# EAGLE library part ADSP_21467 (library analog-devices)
SHARC Processor Auto generated by make-symbol-device-package-bsdl.ulp Rev. 33 Source: ADSP_21467_324_CSPBGA_bsdl.txt http://www.analog.com/static/imported-files/data_sheets/ADSP_21462W_21465W_21467_21469_21469W.pdf
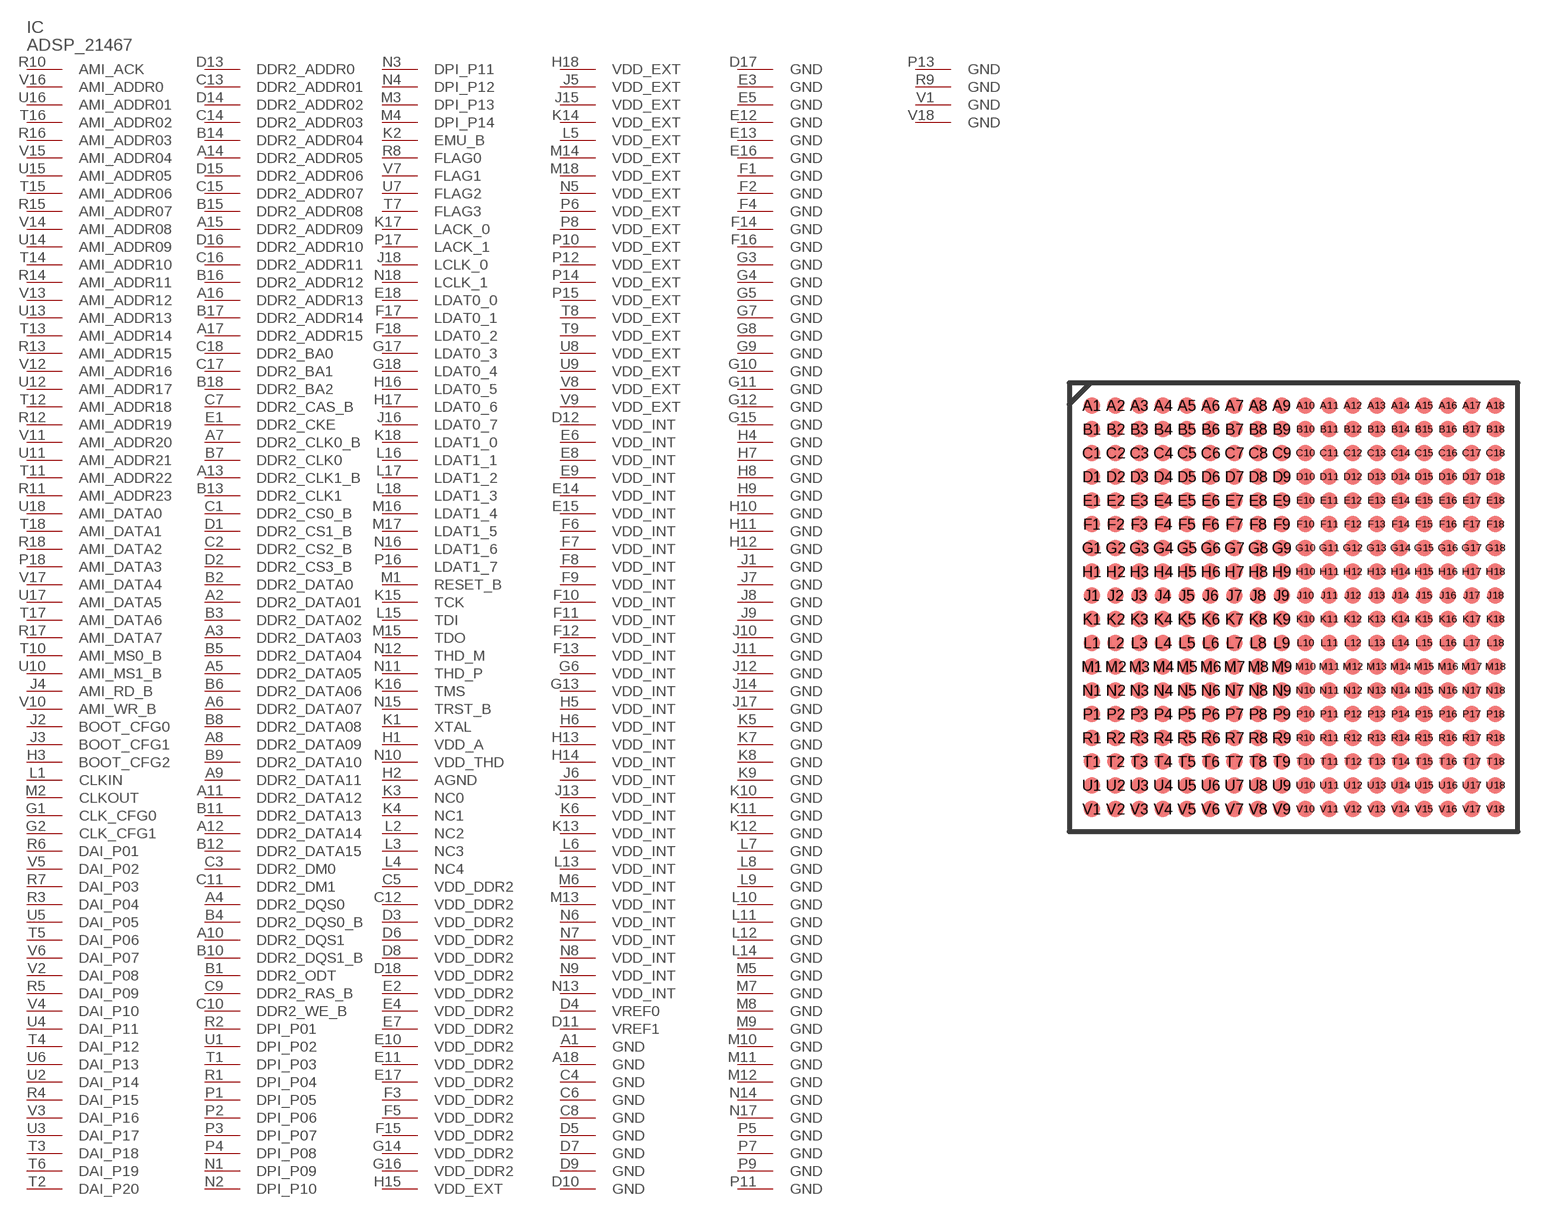
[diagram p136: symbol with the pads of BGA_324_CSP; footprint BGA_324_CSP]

Designator prefix IC

## ADSP_21467 (OC_FARNELL: unknown; OC_NEWARK: unknown)  [BGA_324_CSP]
A1  GND  pwr
A2  DDR2_DATA01
A3  DDR2_DATA03
A4  DDR2_DQS0
A5  DDR2_DATA05
A6  DDR2_DATA07
A7  DDR2_CLK0_B  out
A8  DDR2_DATA09
A9  DDR2_DATA11
A10  DDR2_DQS1
A11  DDR2_DATA12
A12  DDR2_DATA14
A13  DDR2_CLK1_B  out
A14  DDR2_ADDR05  out
A15  DDR2_ADDR09  out
A16  DDR2_ADDR13  out
A17  DDR2_ADDR15  out
A18  GND  pwr
B1  DDR2_ODT  out
B2  DDR2_DATA0
B3  DDR2_DATA02
B4  DDR2_DQS0_B
B5  DDR2_DATA04
B6  DDR2_DATA06
B7  DDR2_CLK0  out
B8  DDR2_DATA08
B9  DDR2_DATA10
B10  DDR2_DQS1_B
B11  DDR2_DATA13
B12  DDR2_DATA15
B13  DDR2_CLK1  out
B14  DDR2_ADDR04  out
B15  DDR2_ADDR08  out
B16  DDR2_ADDR12  out
B17  DDR2_ADDR14  out
B18  DDR2_BA2  out
C1  DDR2_CS0_B  out
C2  DDR2_CS2_B  out
C3  DDR2_DM0  out
C4  GND  pwr
C5  VDD_DDR2  pwr
C6  GND  pwr
C7  DDR2_CAS_B  out
C8  GND  pwr
C9  DDR2_RAS_B  out
C10  DDR2_WE_B  out
C11  DDR2_DM1  out
C12  VDD_DDR2  pwr
C13  DDR2_ADDR01  out
C14  DDR2_ADDR03  out
C15  DDR2_ADDR07  out
C16  DDR2_ADDR11  out
C17  DDR2_BA1  out
C18  DDR2_BA0  out
D1  DDR2_CS1_B  out
D2  DDR2_CS3_B  out
D3  VDD_DDR2  pwr
D4  VREF0  pas
D5  GND  pwr
D6  VDD_DDR2  pwr
D7  GND  pwr
D8  VDD_DDR2  pwr
D9  GND  pwr
D10  GND  pwr
D11  VREF1  pas
D12  VDD_INT  pwr
D13  DDR2_ADDR0  out
D14  DDR2_ADDR02  out
D15  DDR2_ADDR06  out
D16  DDR2_ADDR10  out
D17  GND  pwr
D18  VDD_DDR2  pwr
E1  DDR2_CKE  out
E2  VDD_DDR2  pwr
E3  GND  pwr
E4  VDD_DDR2  pwr
E5  GND  pwr
E6  VDD_INT  pwr
E7  VDD_DDR2  pwr
E8  VDD_INT  pwr
E9  VDD_INT  pwr
E10  VDD_DDR2  pwr
E11  VDD_DDR2  pwr
E12  GND  pwr
E13  GND  pwr
E14  VDD_INT  pwr
E15  VDD_INT  pwr
E16  GND  pwr
E17  VDD_DDR2  pwr
E18  LDAT0_0
F1  GND  pwr
F2  GND  pwr
F3  VDD_DDR2  pwr
F4  GND  pwr
F5  VDD_DDR2  pwr
F6  VDD_INT  pwr
F7  VDD_INT  pwr
F8  VDD_INT  pwr
F9  VDD_INT  pwr
F10  VDD_INT  pwr
F11  VDD_INT  pwr
F12  VDD_INT  pwr
F13  VDD_INT  pwr
F14  GND  pwr
F15  VDD_DDR2  pwr
F16  GND  pwr
F17  LDAT0_1
F18  LDAT0_2
G1  CLK_CFG0  in
G2  CLK_CFG1  in
G3  GND  pwr
G4  GND  pwr
G5  GND  pwr
G6  VDD_INT  pwr
G7  GND  pwr
G8  GND  pwr
G9  GND  pwr
G10  GND  pwr
G11  GND  pwr
G12  GND  pwr
G13  VDD_INT  pwr
G14  VDD_DDR2  pwr
G15  GND  pwr
G16  VDD_DDR2  pwr
G17  LDAT0_3
G18  LDAT0_4
H1  VDD_A  pwr
H2  AGND  pwr
H3  BOOT_CFG2  in
H4  GND  pwr
H5  VDD_INT  pwr
H6  VDD_INT  pwr
H7  GND  pwr
H8  GND  pwr
H9  GND  pwr
H10  GND  pwr
H11  GND  pwr
H12  GND  pwr
H13  VDD_INT  pwr
H14  VDD_INT  pwr
H15  VDD_EXT  pwr
H16  LDAT0_5
H17  LDAT0_6
H18  VDD_EXT  pwr
J1  GND  pwr
J2  BOOT_CFG0  in
J3  BOOT_CFG1  in
J4  AMI_RD_B  out
J5  VDD_EXT  pwr
J6  VDD_INT  pwr
J7  GND  pwr
J8  GND  pwr
J9  GND  pwr
J10  GND  pwr
J11  GND  pwr
J12  GND  pwr
J13  VDD_INT  pwr
J14  GND  pwr
J15  VDD_EXT  pwr
J16  LDAT0_7
J17  GND  pwr
J18  LCLK_0
K1  XTAL  out
K2  EMU_B  out
K3  NC0  pas
K4  NC1  pas
K5  GND  pwr
K6  VDD_INT  pwr
K7  GND  pwr
K8  GND  pwr
K9  GND  pwr
K10  GND  pwr
K11  GND  pwr
K12  GND  pwr
K13  VDD_INT  pwr
K14  VDD_EXT  pwr
K15  TCK  in
K16  TMS  in
K17  LACK_0
K18  LDAT1_0
L1  CLKIN  in
L2  NC2  pas
L3  NC3  pas
L4  NC4  pas
L5  VDD_EXT  pwr
L6  VDD_INT  pwr
L7  GND  pwr
L8  GND  pwr
L9  GND  pwr
L10  GND  pwr
L11  GND  pwr
L12  GND  pwr
L13  VDD_INT  pwr
L14  GND  pwr
L15  TDI  in
L16  LDAT1_1
L17  LDAT1_2
L18  LDAT1_3
M1  RESET_B  in
M2  CLKOUT
M3  DPI_P13
M4  DPI_P14
M5  GND  pwr
M6  VDD_INT  pwr
M7  GND  pwr
M8  GND  pwr
M9  GND  pwr
M10  GND  pwr
M11  GND  pwr
M12  GND  pwr
M13  VDD_INT  pwr
M14  VDD_EXT  pwr
M15  TDO  out
M16  LDAT1_4
M17  LDAT1_5
M18  VDD_EXT  pwr
N1  DPI_P09
N2  DPI_P10
N3  DPI_P11
N4  DPI_P12
N5  VDD_EXT  pwr
N6  VDD_INT  pwr
N7  VDD_INT  pwr
N8  VDD_INT  pwr
N9  VDD_INT  pwr
N10  VDD_THD  pwr
N11  THD_P  pas
N12  THD_M  pas
N13  VDD_INT  pwr
N14  GND  pwr
N15  TRST_B  in
N16  LDAT1_6
N17  GND  pwr
N18  LCLK_1
P1  DPI_P05
P2  DPI_P06
P3  DPI_P07
P4  DPI_P08
P5  GND  pwr
P6  VDD_EXT  pwr
P7  GND  pwr
P8  VDD_EXT  pwr
P9  GND  pwr
P10  VDD_EXT  pwr
P11  GND  pwr
P12  VDD_EXT  pwr
P13  GND  pwr
P14  VDD_EXT  pwr
P15  VDD_EXT  pwr
P16  LDAT1_7
P17  LACK_1
P18  AMI_DATA3
R1  DPI_P04
R2  DPI_P01
R3  DAI_P04
R4  DAI_P15
R5  DAI_P09
R6  DAI_P01
R7  DAI_P03
R8  FLAG0
R9  GND  pwr
R10  AMI_ACK  in
R11  AMI_ADDR23
R12  AMI_ADDR19
R13  AMI_ADDR15
R14  AMI_ADDR11
R15  AMI_ADDR07
R16  AMI_ADDR03
R17  AMI_DATA7
R18  AMI_DATA2
T1  DPI_P03
T2  DAI_P20
T3  DAI_P18
T4  DAI_P12
T5  DAI_P06
T6  DAI_P19
T7  FLAG3
T8  VDD_EXT  pwr
T9  VDD_EXT  pwr
T10  AMI_MS0_B  out
T11  AMI_ADDR22
T12  AMI_ADDR18
T13  AMI_ADDR14
T14  AMI_ADDR10
T15  AMI_ADDR06
T16  AMI_ADDR02
T17  AMI_DATA6
T18  AMI_DATA1
U1  DPI_P02
U2  DAI_P14
U3  DAI_P17
U4  DAI_P11
U5  DAI_P05
U6  DAI_P13
U7  FLAG2
U8  VDD_EXT  pwr
U9  VDD_EXT  pwr
U10  AMI_MS1_B  out
U11  AMI_ADDR21
U12  AMI_ADDR17
U13  AMI_ADDR13
U14  AMI_ADDR09
U15  AMI_ADDR05
U16  AMI_ADDR01
U17  AMI_DATA5
U18  AMI_DATA0
V1  GND  pwr
V2  DAI_P08
V3  DAI_P16
V4  DAI_P10
V5  DAI_P02
V6  DAI_P07
V7  FLAG1
V8  VDD_EXT  pwr
V9  VDD_EXT  pwr
V10  AMI_WR_B  out
V11  AMI_ADDR20
V12  AMI_ADDR16
V13  AMI_ADDR12
V14  AMI_ADDR08
V15  AMI_ADDR04
V16  AMI_ADDR0
V17  AMI_DATA4
V18  GND  pwr

## Footprint BGA_324_CSP (pad centres in mm)
ADSP_21462W_324_CSPBGA_bsdl edit this description Auto generated by make-symbol-device-package-bsdl.ulp Rev. 33 Source: ADSP_21462W_324_CSPBGA_bsdl.txt
smd 0.7 x 0.7: A1 -8.5,8.5; A2 -7.5,8.5; A3 -6.5,8.5; A4 -5.5,8.5; A5 -4.5,8.5; A6 -3.5,8.5; A7 -2.5,8.5; A8 -1.5,8.5; A9 -0.5,8.5; A10 0.5,8.5; A11 1.5,8.5; A12 2.5,8.5; A13 3.5,8.5; A14 4.5,8.5; A15 5.5,8.5; A16 6.5,8.5; A17 7.5,8.5; A18 8.5,8.5; B1 -8.5,7.5; B2 -7.5,7.5; B3 -6.5,7.5; B4 -5.5,7.5; B5 -4.5,7.5; B6 -3.5,7.5; B7 -2.5,7.5; B8 -1.5,7.5; B9 -0.5,7.5; B10 0.5,7.5; B11 1.5,7.5; B12 2.5,7.5; B13 3.5,7.5; B14 4.5,7.5; B15 5.5,7.5; B16 6.5,7.5; B17 7.5,7.5; B18 8.5,7.5; C1 -8.5,6.5; C2 -7.5,6.5; C3 -6.5,6.5; C4 -5.5,6.5; C5 -4.5,6.5; C6 -3.5,6.5; C7 -2.5,6.5; C8 -1.5,6.5; C9 -0.5,6.5; C10 0.5,6.5; C11 1.5,6.5; C12 2.5,6.5; C13 3.5,6.5; C14 4.5,6.5; C15 5.5,6.5; C16 6.5,6.5; C17 7.5,6.5; C18 8.5,6.5; D1 -8.5,5.5; D2 -7.5,5.5; D3 -6.5,5.5; D4 -5.5,5.5; D5 -4.5,5.5; D6 -3.5,5.5; D7 -2.5,5.5; D8 -1.5,5.5; D9 -0.5,5.5; D10 0.5,5.5; D11 1.5,5.5; D12 2.5,5.5; D13 3.5,5.5; D14 4.5,5.5; D15 5.5,5.5; D16 6.5,5.5; D17 7.5,5.5; D18 8.5,5.5; E1 -8.5,4.5; E2 -7.5,4.5; E3 -6.5,4.5; E4 -5.5,4.5; E5 -4.5,4.5; E6 -3.5,4.5; E7 -2.5,4.5; E8 -1.5,4.5; E9 -0.5,4.5; E10 0.5,4.5; E11 1.5,4.5; E12 2.5,4.5; E13 3.5,4.5; E14 4.5,4.5; E15 5.5,4.5; E16 6.5,4.5; E17 7.5,4.5; E18 8.5,4.5; F1 -8.5,3.5; F2 -7.5,3.5; F3 -6.5,3.5; F4 -5.5,3.5; F5 -4.5,3.5; F6 -3.5,3.5; F7 -2.5,3.5; F8 -1.5,3.5; F9 -0.5,3.5; F10 0.5,3.5; F11 1.5,3.5; F12 2.5,3.5; F13 3.5,3.5; F14 4.5,3.5; F15 5.5,3.5; F16 6.5,3.5; F17 7.5,3.5; F18 8.5,3.5; G1 -8.5,2.5; G2 -7.5,2.5; G3 -6.5,2.5; G4 -5.5,2.5; G5 -4.5,2.5; G6 -3.5,2.5; G7 -2.5,2.5; G8 -1.5,2.5; G9 -0.5,2.5; G10 0.5,2.5; G11 1.5,2.5; G12 2.5,2.5; G13 3.5,2.5; G14 4.5,2.5; G15 5.5,2.5; G16 6.5,2.5; G17 7.5,2.5; G18 8.5,2.5; H1 -8.5,1.5; H2 -7.5,1.5; H3 -6.5,1.5; H4 -5.5,1.5; H5 -4.5,1.5; H6 -3.5,1.5; H7 -2.5,1.5; H8 -1.5,1.5; H9 -0.5,1.5; H10 0.5,1.5; H11 1.5,1.5; H12 2.5,1.5; H13 3.5,1.5; H14 4.5,1.5; H15 5.5,1.5; H16 6.5,1.5; H17 7.5,1.5; H18 8.5,1.5; J1 -8.5,0.5; J2 -7.5,0.5; J3 -6.5,0.5; J4 -5.5,0.5; J5 -4.5,0.5; J6 -3.5,0.5; J7 -2.5,0.5; J8 -1.5,0.5; J9 -0.5,0.5; J10 0.5,0.5; J11 1.5,0.5; J12 2.5,0.5; J13 3.5,0.5; J14 4.5,0.5; J15 5.5,0.5; J16 6.5,0.5; J17 7.5,0.5; J18 8.5,0.5; K1 -8.5,-0.5; K2 -7.5,-0.5; K3 -6.5,-0.5; K4 -5.5,-0.5; K5 -4.5,-0.5; K6 -3.5,-0.5; K7 -2.5,-0.5; K8 -1.5,-0.5; K9 -0.5,-0.5; K10 0.5,-0.5; K11 1.5,-0.5; K12 2.5,-0.5; K13 3.5,-0.5; K14 4.5,-0.5; K15 5.5,-0.5; K16 6.5,-0.5; K17 7.5,-0.5; K18 8.5,-0.5; L1 -8.5,-1.5; L2 -7.5,-1.5; L3 -6.5,-1.5; L4 -5.5,-1.5; L5 -4.5,-1.5; L6 -3.5,-1.5; L7 -2.5,-1.5; L8 -1.5,-1.5; L9 -0.5,-1.5; L10 0.5,-1.5; L11 1.5,-1.5; L12 2.5,-1.5; L13 3.5,-1.5; L14 4.5,-1.5; L15 5.5,-1.5; L16 6.5,-1.5; L17 7.5,-1.5; L18 8.5,-1.5; M1 -8.5,-2.5; M2 -7.5,-2.5; M3 -6.5,-2.5; M4 -5.5,-2.5; M5 -4.5,-2.5; M6 -3.5,-2.5; M7 -2.5,-2.5; M8 -1.5,-2.5; M9 -0.5,-2.5; M10 0.5,-2.5; M11 1.5,-2.5; M12 2.5,-2.5; M13 3.5,-2.5; M14 4.5,-2.5; M15 5.5,-2.5; M16 6.5,-2.5; M17 7.5,-2.5; M18 8.5,-2.5; N1 -8.5,-3.5; N2 -7.5,-3.5; N3 -6.5,-3.5; N4 -5.5,-3.5; N5 -4.5,-3.5; N6 -3.5,-3.5; N7 -2.5,-3.5; N8 -1.5,-3.5; N9 -0.5,-3.5; N10 0.5,-3.5; N11 1.5,-3.5; N12 2.5,-3.5; N13 3.5,-3.5; N14 4.5,-3.5; N15 5.5,-3.5; N16 6.5,-3.5; N17 7.5,-3.5; N18 8.5,-3.5; P1 -8.5,-4.5; P2 -7.5,-4.5; P3 -6.5,-4.5; P4 -5.5,-4.5; P5 -4.5,-4.5; P6 -3.5,-4.5; P7 -2.5,-4.5; P8 -1.5,-4.5; P9 -0.5,-4.5; P10 0.5,-4.5; P11 1.5,-4.5; P12 2.5,-4.5; P13 3.5,-4.5; P14 4.5,-4.5; P15 5.5,-4.5; P16 6.5,-4.5; P17 7.5,-4.5; P18 8.5,-4.5; R1 -8.5,-5.5; R2 -7.5,-5.5; R3 -6.5,-5.5; R4 -5.5,-5.5; R5 -4.5,-5.5; R6 -3.5,-5.5; R7 -2.5,-5.5; R8 -1.5,-5.5; R9 -0.5,-5.5; R10 0.5,-5.5; R11 1.5,-5.5; R12 2.5,-5.5; R13 3.5,-5.5; R14 4.5,-5.5; R15 5.5,-5.5; R16 6.5,-5.5; R17 7.5,-5.5; R18 8.5,-5.5; T1 -8.5,-6.5; T2 -7.5,-6.5; T3 -6.5,-6.5; T4 -5.5,-6.5; T5 -4.5,-6.5; T6 -3.5,-6.5; T7 -2.5,-6.5; T8 -1.5,-6.5; T9 -0.5,-6.5; T10 0.5,-6.5; T11 1.5,-6.5; T12 2.5,-6.5; T13 3.5,-6.5; T14 4.5,-6.5; T15 5.5,-6.5; T16 6.5,-6.5; T17 7.5,-6.5; T18 8.5,-6.5; U1 -8.5,-7.5; U2 -7.5,-7.5; U3 -6.5,-7.5; U4 -5.5,-7.5; U5 -4.5,-7.5; U6 -3.5,-7.5; U7 -2.5,-7.5; U8 -1.5,-7.5; U9 -0.5,-7.5; U10 0.5,-7.5; U11 1.5,-7.5; U12 2.5,-7.5; U13 3.5,-7.5; U14 4.5,-7.5; U15 5.5,-7.5; U16 6.5,-7.5; U17 7.5,-7.5; U18 8.5,-7.5; V1 -8.5,-8.5; V2 -7.5,-8.5; V3 -6.5,-8.5; V4 -5.5,-8.5; V5 -4.5,-8.5; V6 -3.5,-8.5; V7 -2.5,-8.5; V8 -1.5,-8.5; V9 -0.5,-8.5; V10 0.5,-8.5; V11 1.5,-8.5; V12 2.5,-8.5; V13 3.5,-8.5; V14 4.5,-8.5; V15 5.5,-8.5; V16 6.5,-8.5; V17 7.5,-8.5; V18 8.5,-8.5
